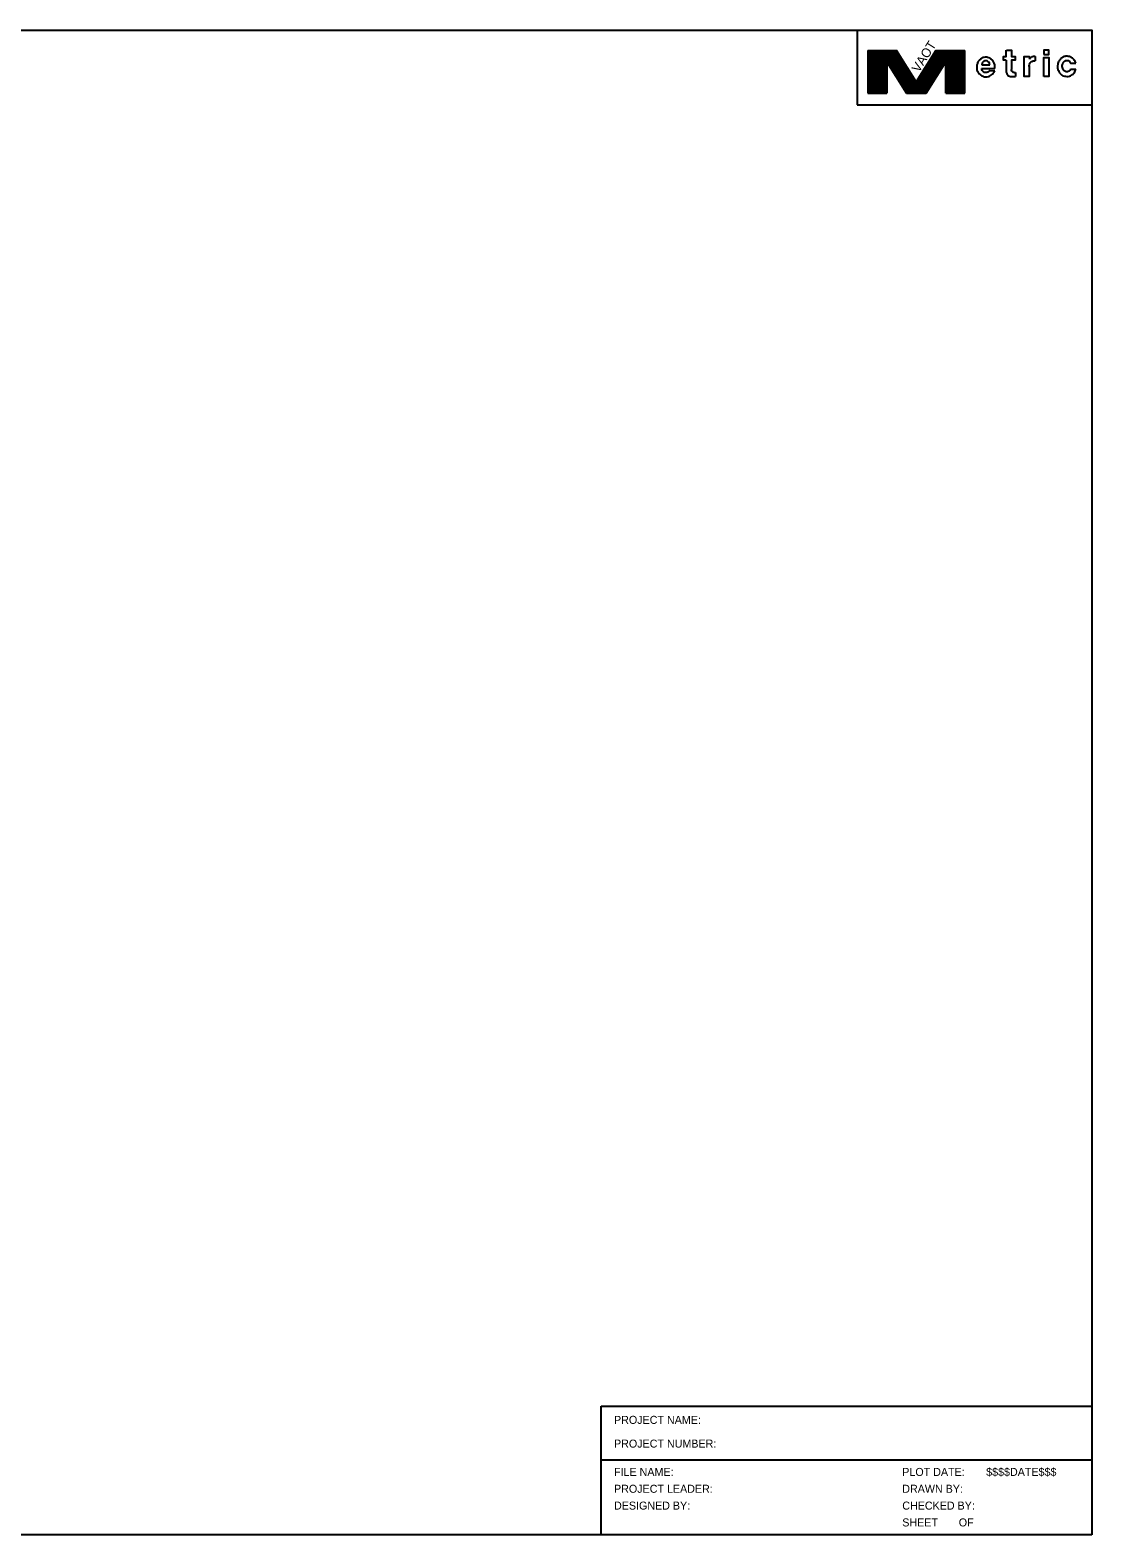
# Model space of a CAD drawing. Extents: x 0 to 199, y 0 to 141.
import ezdxf

# ---------------------------------------------------------------- set-up
doc = ezdxf.new("R2010")
doc.units = 0
doc.layers.add('NBL1', color=7, linetype='Continuous')

msp = doc.modelspace()

# ---------------------------------------------------------------- linework, layer by layer
at = {"layer": 'NBL1'}
for p, q in [((177, 141), (177, 134)), ((178.008, 139.088), (178.008, 135.088)), ((178.008, 139.088), (180.701, 139.088)), ((178.048, 139.088), (178.048, 135.088)), ((178.088, 139.088), (178.088, 135.088)), ((178.128, 139.088), (178.128, 135.088)), ((178.168, 139.088), (178.168, 135.088)), ((178.208, 139.088), (178.208, 135.088)), ((178.248, 139.088), (178.248, 135.088)), ((178.288, 139.088), (178.288, 135.088)), ((178.328, 139.088), (178.328, 135.088)), ((178.368, 139.088), (178.368, 135.088)), ((178.408, 139.088), (178.408, 135.088)), ((178.448, 139.088), (178.448, 135.088)), ((178.488, 139.088), (178.488, 135.088)), ((178.528, 139.088), (178.528, 135.088)), ((178.568, 139.088), (178.568, 135.088)), ((178.608, 139.088), (178.608, 135.088)), ((178.648, 139.088), (178.648, 135.088)), ((178.688, 139.088), (178.688, 135.088)), ((178.728, 139.088), (178.728, 135.088)), ((178.768, 139.088), (178.768, 135.088)), ((178.808, 139.088), (178.808, 135.088)), ((178.848, 139.088), (178.848, 135.088)), ((178.888, 139.088), (178.888, 135.088)), ((178.928, 139.088), (178.928, 135.088)), ((178.968, 139.088), (178.968, 135.088)), ((179.008, 139.088), (179.008, 135.088)), ((179.048, 139.088), (179.048, 135.088)), ((179.088, 139.088), (179.088, 135.088)), ((179.128, 139.088), (179.128, 135.088)), ((179.168, 139.088), (179.168, 135.088)), ((179.208, 139.088), (179.208, 135.088)), ((179.248, 139.088), (179.248, 135.088)), ((179.288, 139.088), (179.288, 135.088)), ((179.328, 139.088), (179.328, 135.088)), ((179.368, 139.088), (179.368, 135.088)), ((179.408, 139.088), (179.408, 135.088)), ((179.448, 139.088), (179.448, 135.088)), ((179.488, 139.088), (179.488, 135.088)), ((179.528, 139.088), (179.528, 135.088)), ((179.568, 139.088), (179.568, 135.088)), ((179.608, 139.088), (179.608, 135.088)), ((179.648, 139.088), (179.648, 135.088)), ((179.688, 139.088), (179.688, 135.088)), ((179.728, 139.088), (179.728, 135.088)), ((179.768, 139.088), (179.768, 135.088)), ((182.268, 135.088), (179.768, 139.068)), ((182.221, 135.088), (179.768, 138.993)), ((182.173, 135.088), (179.768, 138.917)), ((182.126, 135.088), (179.768, 138.842)), ((182.08, 135.088), (179.768, 138.768)), ((182.032, 135.088), (179.768, 138.693)), ((181.985, 135.088), (179.768, 138.617)), ((181.937, 135.088), (179.768, 138.542)), ((181.89, 135.088), (179.768, 138.467)), ((181.842, 135.088), (179.768, 138.39)), ((181.795, 135.088), (179.768, 138.315)), ((181.748, 135.088), (179.768, 138.24)), ((182.315, 135.088), (179.803, 139.088)), ((182.363, 135.088), (179.85, 139.088)), ((182.41, 135.088), (179.898, 139.088)), ((182.457, 135.088), (179.945, 139.088)), ((182.504, 135.088), (179.991, 139.088)), ((182.544, 135.1), (180.039, 139.088)), ((182.544, 135.176), (180.086, 139.088)), ((182.544, 135.251), (180.133, 139.088)), ((182.543, 135.326), (180.18, 139.088)), ((182.544, 135.402), (180.228, 139.088)), ((182.544, 135.477), (180.275, 139.088)), ((182.544, 135.551), (180.323, 139.088)), ((182.544, 135.627), (180.369, 139.088)), ((182.544, 135.702), (180.417, 139.088)), ((182.544, 135.777), (180.464, 139.088)), ((182.544, 135.852), (180.511, 139.088)), ((182.544, 135.928), (180.558, 139.088)), ((182.544, 136.003), (180.605, 139.088)), ((182.51, 136.057), (180.619, 139.066)), ((182.544, 136.079), (180.653, 139.088)), ((182.544, 136.154), (180.701, 139.088)), ((184.905, 139.088), (182.543, 135.326)), ((184.386, 139.088), (182.544, 136.154)), ((184.433, 139.088), (182.544, 136.079)), ((184.48, 139.088), (182.544, 136.004)), ((184.527, 139.088), (182.544, 135.928)), ((184.575, 139.088), (182.544, 135.852)), ((184.622, 139.088), (182.544, 135.777)), ((184.669, 139.088), (182.544, 135.702)), ((184.717, 139.088), (182.544, 135.627)), ((184.764, 139.088), (182.544, 135.551)), ((184.811, 139.088), (182.544, 135.477)), ((184.858, 139.088), (182.544, 135.402)), ((184.953, 139.088), (182.544, 135.251)), ((185, 139.088), (182.544, 135.176)), ((185.047, 139.088), (182.544, 135.1)), ((185.095, 139.088), (182.584, 135.088)), ((185.142, 139.088), (182.631, 135.088)), ((185.188, 139.088), (182.677, 135.088)), ((185.235, 139.088), (182.724, 135.088)), ((185.283, 139.088), (182.772, 135.088)), ((185.319, 139.07), (182.819, 135.088)), ((185.319, 138.995), (182.866, 135.088)), ((185.319, 138.919), (182.914, 135.088)), ((185.319, 138.843), (182.961, 135.088)), ((185.319, 138.768), (183.009, 135.088)), ((185.319, 138.695), (183.055, 135.088)), ((185.319, 138.619), (183.102, 135.088)), ((185.319, 138.543), (183.15, 135.088)), ((185.319, 138.468), (183.197, 135.088)), ((185.319, 138.393), (183.244, 135.088)), ((185.319, 138.317), (183.292, 135.088)), ((185.319, 138.242), (183.339, 135.088)), ((184.386, 139.088), (187.079, 139.088)), ((185.319, 135.088), (185.319, 139.088)), ((185.359, 135.088), (185.359, 139.088)), ((185.399, 135.088), (185.399, 139.088)), ((185.439, 135.088), (185.439, 139.088)), ((185.479, 135.088), (185.479, 139.088)), ((185.519, 135.088), (185.519, 139.088)), ((185.559, 135.088), (185.559, 139.088)), ((185.599, 135.088), (185.599, 139.088)), ((185.639, 135.088), (185.639, 139.088)), ((185.679, 135.088), (185.679, 139.088)), ((185.719, 135.088), (185.719, 139.088)), ((185.759, 135.088), (185.759, 139.088)), ((185.799, 135.088), (185.799, 139.088)), ((185.839, 135.088), (185.839, 139.088)), ((185.879, 135.088), (185.879, 139.088)), ((185.919, 135.088), (185.919, 139.088)), ((185.959, 135.088), (185.959, 139.088)), ((185.999, 135.088), (185.999, 139.088)), ((186.039, 135.088), (186.039, 139.088)), ((186.079, 135.088), (186.079, 139.088)), ((186.119, 135.088), (186.119, 139.088)), ((186.159, 135.088), (186.159, 139.088)), ((186.199, 135.088), (186.199, 139.088)), ((186.239, 135.088), (186.239, 139.088)), ((186.279, 135.088), (186.279, 139.088)), ((186.319, 135.088), (186.319, 139.088)), ((186.359, 135.088), (186.359, 139.088)), ((186.399, 135.088), (186.399, 139.088)), ((186.439, 135.088), (186.439, 139.088)), ((186.479, 135.088), (186.479, 139.088)), ((186.519, 135.088), (186.519, 139.088)), ((186.559, 135.088), (186.559, 139.088)), ((186.599, 135.088), (186.599, 139.088)), ((186.639, 135.088), (186.639, 139.088)), ((186.679, 135.088), (186.679, 139.088)), ((186.719, 135.088), (186.719, 139.088)), ((186.759, 135.088), (186.759, 139.088)), ((186.799, 135.088), (186.799, 139.088)), ((186.839, 135.088), (186.839, 139.088)), ((186.879, 135.088), (186.879, 139.088)), ((186.919, 135.088), (186.919, 139.088)), ((186.959, 135.088), (186.959, 139.088)), ((186.999, 135.088), (186.999, 139.088)), ((187.039, 135.088), (187.039, 139.088)), ((187.079, 135.088), (187.079, 139.088)), ((181.702, 135.088), (179.768, 138.167)), ((181.654, 135.088), (179.768, 138.09)), ((179.78, 135.088), (179.78, 138.037)), ((179.78, 138.037), (181.622, 135.088)), ((185.319, 138.166), (183.386, 135.088)), ((185.319, 138.093), (183.432, 135.088)), ((183.465, 135.088), (185.307, 138.037)), ((185.307, 138.037), (185.307, 135.088)), ((177, 134), (199, 134)), ((178.008, 135.088), (179.78, 135.088)), ((181.622, 135.088), (183.465, 135.088)), ((185.307, 135.088), (187.079, 135.088)), ((153.001, 12.063), (199, 12.063)), ((153.001, 0), (153.001, 12.063)), ((153.001, 7.047), (199, 7.047))]:
    msp.add_line(p, q, dxfattribs=at)
msp.add_lwpolyline([(199, 0), (0, 0), (0, 141), (199, 141)], close=True, dxfattribs=at)
for points in [[(189.914, 137.409), (189.914, 137.487), (189.914, 137.604), (189.894, 137.739), (189.836, 137.895), (189.778, 138.03), (189.701, 138.147), (189.642, 138.223), (189.566, 138.282), (189.487, 138.32), (189.429, 138.359), (189.333, 138.398), (189.216, 138.437), (189.139, 138.456), (189.062, 138.456), (188.983, 138.456), (188.887, 138.437), (188.81, 138.417), (188.751, 138.398), (188.694, 138.379), (188.616, 138.32), (188.558, 138.282), (188.481, 138.224), (188.423, 138.147), (188.364, 138.088), (188.325, 138.011), (188.287, 137.933), (188.267, 137.855), (188.229, 137.759), (188.209, 137.661), (188.209, 137.545), (188.209, 137.391), (188.228, 137.256), (188.267, 137.158), (188.325, 137.061), (188.364, 137.004), (188.441, 136.887), (188.519, 136.828), (188.596, 136.77), (188.693, 136.713), (188.771, 136.673), (188.867, 136.635), (188.964, 136.616), (189.081, 136.616), (189.197, 136.635), (189.313, 136.654), (189.41, 136.693), (189.487, 136.731), (189.603, 136.809), (189.681, 136.867), (189.759, 136.964), (189.836, 137.061), (189.894, 137.177)], [(190.979, 138.184), (190.728, 138.184), (190.728, 138.514), (190.979, 138.514), (190.98, 139.114)], [(190.979, 138.184), (190.979, 137.061)], [(190.999, 139.114), (191.463, 139.114), (191.463, 138.514), (191.812, 138.514), (191.812, 138.184), (191.463, 138.184), (191.463, 137.312)], [(192.645, 136.653), (192.645, 138.513)], [(193.13, 137.68), (193.129, 136.653), (192.645, 136.653), (192.645, 138.513), (193.13, 138.513), (193.149, 138.261)], [(193.149, 138.261), (193.187, 138.339), (193.226, 138.398), (193.265, 138.435), (193.342, 138.494), (193.382, 138.513), (193.42, 138.533), (193.517, 138.552), (193.536, 138.552), (193.594, 138.552), (193.614, 138.552), (193.69, 138.533)], [(193.69, 138.533), (193.69, 138.126)], [(194.484, 136.653), (194.485, 138.435), (194.95, 138.435), (194.949, 136.653), (194.484, 136.653)], [(194.485, 138.706), (194.95, 138.706), (194.95, 139.113), (194.485, 139.113), (194.485, 138.706)], [(197.487, 137.912), (197.448, 137.989), (197.43, 138.048), (197.371, 138.145), (197.333, 138.202), (197.294, 138.26), (197.235, 138.318), (197.178, 138.377), (197.1, 138.416), (197.042, 138.454), (196.965, 138.493), (196.887, 138.512), (196.771, 138.532), (196.674, 138.552), (196.558, 138.552), (196.48, 138.532), (196.403, 138.512), (196.326, 138.493), (196.267, 138.454), (196.19, 138.416), (196.111, 138.357), (196.055, 138.3), (196.015, 138.26), (195.957, 138.183), (195.918, 138.125), (195.879, 138.048), (195.841, 137.97), (195.822, 137.873), (195.803, 137.776), (195.783, 137.641), (195.783, 137.466), (195.822, 137.311), (195.86, 137.215), (195.899, 137.118), (195.976, 137.002), (196.034, 136.923), (196.111, 136.846), (196.19, 136.788), (196.286, 136.73), (196.422, 136.691), (196.518, 136.672), (196.635, 136.653), (196.79, 136.653), (196.887, 136.691), (197.002, 136.729), (197.1, 136.788), (197.177, 136.826), (197.235, 136.885), (197.294, 136.942), (197.333, 137.001), (197.39, 137.078), (197.429, 137.175), (197.468, 137.253), (197.487, 137.33)], [(188.655, 137.409), (189.914, 137.409)], [(189.429, 137.215), (189.371, 137.158), (189.314, 137.1), (189.255, 137.061), (189.158, 137.022), (189.062, 137.022), (188.983, 137.022), (188.926, 137.041), (188.848, 137.1), (188.79, 137.139), (188.732, 137.216), (188.693, 137.293), (188.674, 137.352), (188.655, 137.409)], [(189.429, 137.758), (189.41, 137.836), (189.39, 137.913), (189.333, 137.991), (189.255, 138.049), (189.178, 138.107), (189.12, 138.127), (189.062, 138.127), (189.003, 138.127), (188.964, 138.107), (188.907, 138.088), (188.868, 138.068), (188.829, 138.049), (188.79, 138.01), (188.771, 137.992), (188.732, 137.933), (188.712, 137.875), (188.694, 137.816), (188.693, 137.758)], [(188.693, 137.758), (189.429, 137.758)], [(189.429, 137.215), (189.894, 137.177)], [(190.979, 137.061), (190.998, 136.983), (191.017, 136.924), (191.037, 136.867), (191.076, 136.809), (191.133, 136.751), (191.192, 136.712), (191.269, 136.672), (191.385, 136.653)], [(191.715, 137.022), (191.637, 137.041), (191.579, 137.079), (191.541, 137.118), (191.502, 137.157), (191.463, 137.235), (191.463, 137.312)], [(191.715, 137.022), (191.831, 137.022)], [(191.831, 137.022), (191.831, 136.653)], [(193.13, 137.603), (193.13, 137.68), (193.149, 137.796), (193.187, 137.874), (193.226, 137.932), (193.284, 137.99), (193.362, 138.048), (193.438, 138.087), (193.497, 138.106), (193.555, 138.126), (193.614, 138.126), (193.69, 138.126)], [(196.983, 137.35), (196.964, 137.292), (196.926, 137.214), (196.867, 137.157), (196.79, 137.118), (196.712, 137.078), (196.654, 137.078), (196.577, 137.078), (196.461, 137.137), (196.403, 137.175), (196.325, 137.253), (196.286, 137.33), (196.267, 137.409), (196.248, 137.486), (196.228, 137.582), (196.228, 137.679), (196.248, 137.776), (196.267, 137.854), (196.306, 137.951), (196.422, 138.086), (196.48, 138.125), (196.519, 138.145), (196.596, 138.164), (196.674, 138.164), (196.732, 138.164), (196.809, 138.145), (196.867, 138.106), (196.906, 138.066), (196.926, 138.028), (196.946, 137.989), (196.965, 137.931), (196.983, 137.893)], [(196.983, 137.893), (197.487, 137.912)], [(196.983, 137.35), (197.487, 137.33)], [(191.385, 136.653), (191.618, 136.653), (191.831, 136.653)], [(196.654, 136.711), (196.654, 136.711)]]:
    msp.add_lwpolyline(points, dxfattribs=at)

# ---------------------------------------------------------------- texts
msp.add_text('VAOT', height=0.8626, rotation=57.99715, dxfattribs=at).set_placement((182.789, 136.964))
for s, p in [('PROJECT NAME:', (154.22, 10.404)), ('PROJECT NUMBER:', (154.22, 8.179)), ('FILE NAME:', (154.22, 5.525)), ('PLOT DATE:', (181.23, 5.525)), ('$$$$DATE$$$', (189.092, 5.525)), ('PROJECT LEADER:', (154.22, 3.948)), ('DRAWN BY:', (181.23, 3.948)), ('DESIGNED BY:', (154.22, 2.371)), ('CHECKED BY:', (181.23, 2.371)), ('SHEET       OF', (181.23, 0.794))]:
    msp.add_text(s, height=0.75, dxfattribs=at).set_placement(p)

doc.saveas('drawing.dxf')
